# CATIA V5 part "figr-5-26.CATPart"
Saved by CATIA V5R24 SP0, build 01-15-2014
Part number: Part1
Bounding box of the stored display mesh (mm): x -75 to 75, y -100 to 100, z 0 to 53
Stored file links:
  D:\KAVITA\CATIA V5-6R2014 Project_ Kavita\CATIA V5-6R2014_partfiles\Partfiles\c05_catia_v5-6r2014_prt\figr-5-26.CATPart
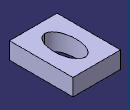
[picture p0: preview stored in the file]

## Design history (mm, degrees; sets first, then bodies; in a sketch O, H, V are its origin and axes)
Body1 (main body)
  Sketch1 on xy-plane, origin (0, 0, 0), H (1, 0, 0), V (0, 1, 0)
    line L1 (-75, 100) -> (75, 100)
    line L2 (75, 100) -> (75, -100)
    line L3 (75, -100) -> (-75, -100)
    line L4 (-75, -100) -> (-75, 100)
    axis line L5 (75, -100) -> (-75, 100)
    length L3 = 150
    length L2 = 200
    horizontal: L1 H, L3 H
    vertical: L2 V, L4 V
    midpoint: L5 O
  Pad1: profile Sketch1, direction (0, 0, 1), length 53
  Sketch2 on face of Pad1, origin (0, 0, 53), H (1, 0, 0), V (0, 1, 0)
    ellipse A1 centre (0, 0) semi-axes 63.781, 34.5424 rotation 270
    point P1 (0, -63.781)
    point P2 (34.5424, 0)
    coincidence: P1 V, P2 H, A1 P1, A1 P2
  Pocket1: profile Sketch2, direction (0, 0, -1), through (limit type 3)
